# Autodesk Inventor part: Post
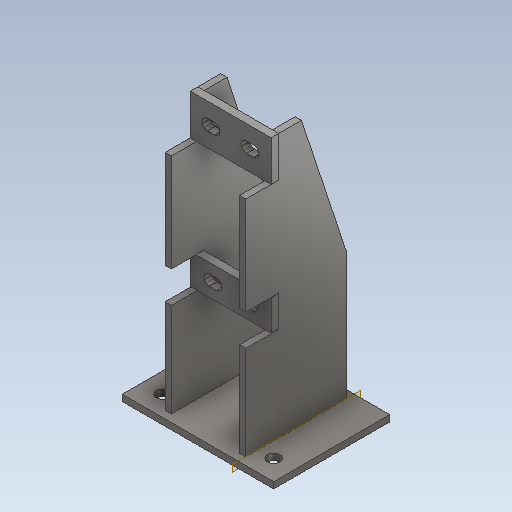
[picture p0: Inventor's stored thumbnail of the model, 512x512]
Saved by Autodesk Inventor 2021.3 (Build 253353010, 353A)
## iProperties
Created: 2019-06
Part Number: Post
Material: Steel, Galvanized
Document SubType Name: Modeling
Designer: u1426
Density: 7.85 g/cm^3
Appearance: Galvanized
Author: u1426
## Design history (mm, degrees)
sketch "Sketch2"
  geometry: L1 (-190.5, 0)-(190.5, 0); L2 (190.5, 0)-(190.5, 292.1); L3 (-190.5, 292.1)-(-190.5, 0); L4 (190.5, 292.1)-(0.198, 292.1); L5 (-0.198, 292.1)-(-190.5, 292.1); L6 (0.198, 292.1)-(0.198, 292.894); L7 (0.198, 292.894)-(-0.198, 292.894); L8 (-0.198, 292.894)-(-0.198, 292.1); 1 further point
  constraints: 16 end point, 3 perpendicular, 2 horizontal, 1 collinear, 1 vertical
  dimensions: "d116" = 292.1 distance of L1.end L2.end; "d117" = 292.1 distance of L3.start L1.start; "d118" = 190.5 distance from line of point (0, 0) L3; "d119" = 190.5 distance from line of point (0, 0) L2; "d120" = 0.79375 distance of L4.end L6.end; "d121" = 0.39687 distance of L6.end L7.end; "d122" = 0.79375 distance of L7.end L5.start (= d120); "d123" = 190.30156 distance of L2.end L4.end (= d119 - 0.5 x d121)
extrude "BasePlate" new body sketch "Sketch2" distance "d22" = 15.875; taper "d23" = 0 deg
sketch "Sketch3"
  geometry: L1 (190.5, 0)-(190.5, 292.1) reference; L2 (-190.5, 292.1)-(-190.5, 0) reference; 4 further points
  dimensions: "d32" = 50.8 distance from line of point (139.7, 50.8) L1; "d33" = 50.8 vertical distance of point (-139.7, 50.8) point (0, 0); "d34" = 50.8 horizontal distance of point (139.7, 50.8) L1.start; "d35" = 50.8 vertical distance of point (0, 241.3) L1.end; "d36" = 190.5 horizontal distance of point (0, 241.3) L1.end; "d114" = 50.8 distance from line of point (-139.7, 50.8) L2
hole "Hole1" sketch "Sketch3" at (-139.7, 50.8), (139.7, 50.8), (0, 241.3) diameter "d24" = 31.75; stored, may be unused: countersink angle "d28" = 82 deg, drill point angle "d30" = 118 deg; dims "d25" = 19.05, "d26" = 9.525, "d27" = 6.35, "d29" = 19.05
workplane "Work Plane1"
sketch "Sketch4"
  geometry: L1 (-15.875, 0)-(-15.875, 292.1) reference; L2 (-15.875, 19.05)-(-15.875, 273.05); L3 (-15.875, 19.05)-(-252.412, 19.05); L4 (-252.412, 19.05)-(-252.412, 101.6); L5 (-252.412, 101.6)-(-331.787, 101.6); L6 (-331.787, 101.6)-(-331.787, 19.05); L7 (-331.787, 19.05)-(-577.85, 19.05); L8 (-577.85, 19.05)-(-577.85, 101.6); L9 (-577.85, 101.6)-(-679.45, 101.6); L10 (-679.45, 101.6)-(-679.45, 158.75); L11 (-15.875, 273.05)-(-333.375, 273.05); L12 (-333.375, 273.05)-(-679.45, 158.75); 1 further point
  constraints: 22 end point, 4 point on line, 3 horizontal, 2 vertical
  dimensions: "d38" = 254 distance of L2.start L2.end; "d50" = 236.5375 distance of L2.start L3.end; "d51" = 82.55 distance of L3.end L4.end; "d52" = 79.375 distance of L4.end L5.end; "d53" = 82.55 distance of L5.end L6.end; "d54" = 246.0625 distance of L6.end L7.end; "d55" = 82.55 distance of L7.end L8.end (derived); "d56" = 101.6 distance of L8.end L9.end; "d57" = 57.15 distance of L9.end L10.end; "d58" = 317.5 distance of L2.end L11.end; "d59" = 19.05 distance of L2.start L1.start; "d60" = 346.075 horizontal distance of L10.end L11.end; "d61" = 114.3 vertical distance of L10.end L11.end
extrude "SidePlate" new body sketch "Sketch4" distance "d62" = 15.875; taper "d63" = 0 deg
pattern_linear "Rectangular Pattern1" dims "d66" = 187.325
sketch "Sketch6"
  geometry: L1 (0, 79.375)-(0, 0) reference; L2 (0, 1.587)-(-203.2, 1.587); L3 (-203.2, 1.587)-(-203.2, 77.788); L4 (-203.2, 0)-(-203.2, 79.375) reference; L5 (-203.2, 77.788)-(0, 77.788); L6 (0, 77.788)-(0, 1.587); 1 further point
  constraints: 8 end point, 2 horizontal, 2 point on line
  dimensions: "d71" = 203.2 distance of L2.start L2.end; "d72" = 76.2 distance of L2.end L3.end; "d73" = 203.2 distance of L3.end L5.end
extrude "LowerBackPlate" new body sketch "Sketch6" distance "d74" = 19.05; taper "d75" = 0 deg
sketch "Sketch7"
  geometry: L1 (0, 101.6)-(-203.2, 101.6); L2 (-203.2, 101.6)-(-203.2, 0); L3 (-203.2, 101.6)-(-203.2, -244.475) reference; L4 (-203.2, 0)-(0, 0); L5 (0, -244.475)-(0, 101.6) reference; L6 (0, 0)-(0, 101.6); 1 further point
  constraints: 8 end point, 2 horizontal, 1 point on line
  dimensions: "d77" = 101.6 distance of L1.end L2.end; "d78" = 203.2 distance of L2.end L4.end
extrude "UpperBackPlate" new body sketch "Sketch7" distance "d79" = 19.05; taper "d80" = 0 deg
sketch "Sketch8"
  geometry: L1 (-203.2, 1.588)-(0, 1.588) reference; L2 (0, 77.787)-(-203.2, 77.787) reference; L3 (-155.543, 53.181)-(-137.319, 53.181); L4 (-155.543, 26.194)-(-137.319, 26.194); L5 (-47.657, 53.181)-(-65.881, 53.181); L6 (-47.657, 26.194)-(-65.881, 26.194); A1 r 13.494 centre (-155.543, 39.688) between (-155.543, 53.181) and (-155.543, 26.194); A2 r 13.494 centre (-137.319, 39.688) between (-137.319, 26.194) and (-137.319, 53.181); A3 r 13.494 centre (-47.657, 39.688) between (-47.657, 26.194) and (-47.657, 53.181); A4 r 13.494 centre (-65.881, 39.688) between (-65.881, 53.181) and (-65.881, 26.194); 1 further point
  constraints: 8 end point, 8 point on circle, 4 centre point, 4 tangent, 2 horizontal
extrude "Extrusion6" cut sketch "Sketch8" extent not by distance; stored distance "d86" = 0; taper "d87" = 0 deg
sketch "Sketch9"
  geometry: L1 (0, 101.6)-(-203.2, 101.6) reference; L2 (-203.2, 0)-(0, 0) reference; L3 (-159.544, 64.294)-(-142.081, 64.294); L4 (-159.544, 37.306)-(-142.081, 37.306); L5 (-43.656, 64.294)-(-61.119, 64.294); L6 (-43.656, 37.306)-(-61.119, 37.306); A1 r 13.494 centre (-159.544, 50.8) between (-159.544, 64.294) and (-159.544, 37.306); A2 r 13.494 centre (-142.081, 50.8) between (-142.081, 37.306) and (-142.081, 64.294); A3 r 13.494 centre (-43.656, 50.8) between (-43.656, 37.306) and (-43.656, 64.294); A4 r 13.494 centre (-61.119, 50.8) between (-61.119, 64.294) and (-61.119, 37.306); 1 further point
  constraints: 8 end point, 8 point on circle, 4 centre point, 4 tangent, 1 horizontal
extrude "Extrusion7" cut sketch "Sketch9" extent not by distance; stored distance "d99" = 19.05; taper "d100" = 0 deg
body "Solid2"
body "Solid3"
body "Solid4"
body "Solid5"
other parameters: "d37" = -88.9, "sa_0" = 4
